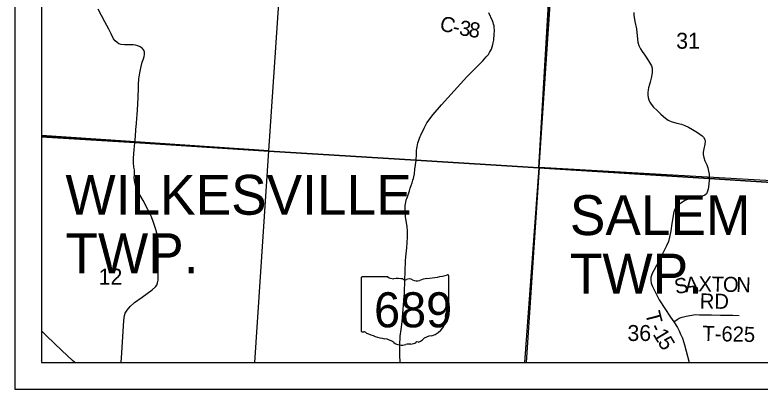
# Model space of a CAD drawing. Extents: x 0 to 34, y 0 to 22.
# Drawn here: x 2 to 4.807, y 14 to 15.408 of the extents above; entities that cross this region are included whole.
import ezdxf

# ---------------------------------------------------------------- set-up
doc = ezdxf.new("R2010")
doc.units = 0
for name, color, linetype in [('GM_X_Corporation', 7, 'Continuous'), ('GM_X_County_Road_Text', 7, 'Continuous'), ('GM_X_Section_Text', 7, 'Continuous'), ('GM_X_State_Location', 7, 'Continuous'), ('GM_X_State_Route', 7, 'Continuous'), ('GM_X_State_Shield', 7, 'Continuous'), ('GM_X_Township_Road', 7, 'Continuous'), ('GM_X_Township_Road_Text', 7, 'Continuous'), ('GM_X_Township_Text', 7, 'Continuous'), ('SH_Data', 7, 'Continuous')]:
    doc.layers.add(name, color=color, linetype=linetype)

msp = doc.modelspace()

# ---------------------------------------------------------------- linework, layer by layer
at = {"layer": 'GM_X_Corporation'}
msp.add_lwpolyline([(2.1, 20.9), (2.1, 14.9497), (2.4519, 14.9275), (2.9562, 14.8958), (3.5107, 14.8614), (3.9742, 14.8327), (4.0069, 15.4088), (4.03, 15.7625), (4.0425, 15.9604), (4.0732, 16.4197), (4.1048, 16.7908), (4.1087, 16.8515), (4.1128, 16.8828), (4.1159, 16.9184), (4.1162, 16.9397), (4.1215, 17.0136), (4.1603, 17.6679)], dxfattribs=at)
for points in [[(2.1, 15.9854), (2.1, 14.9539), (2.9567, 14.8961), (3.0263, 15.9353)], [(4.0444, 15.8589), (5.0732, 15.7926), (5.0032, 14.775), (3.9752, 14.8336)], [(2.1, 14.9539), (2.1, 14.1), (2.9042, 14.1), (2.9567, 14.8961)], [(3.9197, 14.1), (8.9, 14.1), (8.9, 14.5351), (8.0587, 14.59), (7.0121, 14.6499), (6.0453, 14.7107), (5.2037, 14.7544), (4.6148, 14.7919), (3.9742, 14.8327)], [(3.9255, 14.1), (4.958, 14.1), (5.0032, 14.775), (3.9752, 14.8336)]]:
    msp.add_lwpolyline(points, close=True, dxfattribs=at)
at = {"layer": 'GM_X_State_Route'}
for points in [[(3.4508, 14.1), (3.4502, 14.1289), (3.45, 14.162), (3.4497, 14.177), (3.4507, 14.188), (3.4518, 14.1994), (3.4549, 14.224), (3.4575, 14.2433), (3.4593, 14.2539), (3.4672, 14.3623), (3.4693, 14.4102), (3.4705, 14.4428), (3.4713, 14.4824), (3.4726, 14.4977), (3.4762, 14.5314), (3.4777, 14.5517), (3.4787, 14.5719), (3.4787, 14.5854), (3.4787, 14.594), (3.4783, 14.6008), (3.4778, 14.6059), (3.4773, 14.611), (3.4759, 14.6195), (3.4729, 14.6411), (3.4715, 14.648), (3.4708, 14.6556), (3.4703, 14.6622), (3.4697, 14.6718), (3.4697, 14.6786), (3.47, 14.6844), (3.4703, 14.6908), (3.4718, 14.6969), (3.4728, 14.7021), (3.4744, 14.7119), (3.476, 14.7178), (3.4785, 14.7239), (3.486, 14.7466), (3.4895, 14.7563), (3.4927, 14.7663), (3.4963, 14.7756), (3.4993, 14.7857), (3.5011, 14.792), (3.5024, 14.7988), (3.5047, 14.8095), (3.5071, 14.8273), (3.5109, 14.8597), (3.511, 14.8609), (3.5125, 14.8847), (3.5132, 14.8973), (3.5143, 14.9053), (3.5148, 14.9116), (3.5161, 14.9198), (3.5178, 14.9266), (3.5199, 14.9333), (3.5245, 14.9448), (3.5271, 14.9507), (3.5295, 14.9562), (3.5413, 14.9816), (3.5477, 14.994), (3.5523, 15.0019), (3.575, 15.0335), (3.6065, 15.0695), (3.7027, 15.175), (3.7273, 15.2003), (3.7621, 15.2352), (3.7751, 15.2505), (3.7837, 15.2598), (3.7881, 15.2667), (3.7918, 15.2729), (3.7953, 15.2793), (3.7982, 15.2884), (3.8, 15.2968), (3.8018, 15.303), (3.8035, 15.3128), (3.8043, 15.3207), (3.8051, 15.3295), (3.8059, 15.3383), (3.8064, 15.346), (3.8062, 15.3526), (3.8059, 15.3601), (3.8049, 15.3676), (3.8031, 15.3737), (3.801, 15.3801), (3.799, 15.3863), (3.7855, 15.4156)], [(2.2253, 14.1), (2.2166, 14.1079), (2.1773, 14.1453), (2.1198, 14.1993), (2.1095, 14.21), (2.1, 14.2193)]]:
    msp.add_lwpolyline(points, dxfattribs=at)
at = {"layer": 'GM_X_State_Shield'}
for p, q in [((3.3044, 14.4184), (3.3044, 14.2183)), ((3.4042, 14.4219), (3.3077, 14.4219)), ((3.634, 14.3221), (3.634, 14.4268)), ((3.634, 14.3222), (3.634, 14.3221))]:
    msp.add_line(p, q, dxfattribs=at)
for centre, major_axis, start_param, end_param in [((3.5166, 14.6947), (0.3495, 0), 4.814394, 5.042369), ((3.6304, 14.4272), (0.00367, 0), 6.141152, 7.989035), ((3.3082, 14.4188), (0.00382, 0), 1.712693, 3.28349), ((3.4272, 14.4451), (0.037, 0), 4.042523, 4.731795), ((3.4395, 14.3095), (0.133, 0), 1.404758, 1.657858), ((3.4696, 14.4199), (0.0107, 0), 3.836095, 5.185415), ((3.4853, 14.3967), (0.0222, 0), 0.950623, 2.079405), ((3.514, 14.4285), (0.0267, 0), 4.081561, 5.145723), ((3.5612, 14.3607), (0.0703, 0), 1.699011, 2.107814), ((3.6332, 14.3144), (0.00568, 0), 1.883978, 3.671073), ((3.6301, 14.3217), (0.00393, 0), 5.05454, 6.418171), ((3.6472, 14.2783), (0.0248, 0), 2.387724, 3.262537), ((3.597, 14.3012), (0.0341, 0), 5.934695, 6.695948), ((3.5362, 14.265), (0.0874, 0), 5.101752, 6.440018), ((3.3082, 14.2179), (0.00385, 0), 3.00124, 4.508301), ((3.3088, 14.2383), (0.0294, 0), 4.665946, 4.897461), ((3.3148, 14.2067), (0.0106, 0), 0.519207, 1.627899), ((3.4487, 14.3865), (0.2524, 0), 4.195997, 4.488961), ((3.3734, 14.1284), (0.079, 0), 0.823519, 1.323587), ((3.4914, 14.1908), (0.0267, 0), 4.691044, 5.507374), ((3.5156, 14.1714), (0.00752, 0), 1.147584, 2.315152), ((3.5124, 14.1989), (0.0282, 0), 4.937069, 5.64225), ((3.573, 14.1621), (0.0479, 0), 1.647645, 2.488434), ((3.4588, 14.2058), (0.0501, 0), 4.026481, 4.996735), ((3.4878, 14.1366), (0.0412, 0), 1.495662, 1.94098)]:
    msp.add_ellipse(centre, major_axis=major_axis, ratio=0.8, start_param=start_param, end_param=end_param, dxfattribs=at)
at = {"layer": 'GM_X_Township_Road'}
for points in [[(2.4521, 14.927), (2.4537, 14.9508), (2.456, 14.977), (2.4584, 15), (2.4594, 15.0193), (2.4603, 15.0322), (2.4626, 15.0706), (2.4657, 15.1298), (2.4658, 15.1459), (2.4672, 15.167), (2.4695, 15.1827), (2.4721, 15.1963), (2.4752, 15.2141), (2.4791, 15.2301), (2.4838, 15.2433), (2.4865, 15.2522), (2.4887, 15.2594), (2.4882, 15.2684), (2.4857, 15.2758), (2.4795, 15.2828), (2.4721, 15.288), (2.4632, 15.2922), (2.4546, 15.2948), (2.4454, 15.2962), (2.4131, 15.2959), (2.4006, 15.2971), (2.3917, 15.2999), (2.385, 15.3044), (2.3782, 15.311), (2.3716, 15.3184), (2.3623, 15.3371), (2.3532, 15.3543), (2.3387, 15.3827), (2.314, 15.4304)], [(4.3314, 15.4177), (4.3309, 15.4073), (4.3355, 15.3836), (4.3411, 15.356), (4.3438, 15.3292), (4.3468, 15.3058), (4.3499, 15.2929), (4.3564, 15.2803), (4.3628, 15.2701), (4.3724, 15.2563), (4.3868, 15.2354), (4.3947, 15.2233), (4.3978, 15.2162), (4.4, 15.208), (4.4006, 15.2005), (4.4, 15.1902), (4.3963, 15.1703), (4.3927, 15.1551), (4.3905, 15.1458), (4.3866, 15.1338), (4.3849, 15.1256), (4.384, 15.1163), (4.3842, 15.1056), (4.3854, 15.0979), (4.3874, 15.0883), (4.3911, 15.0794), (4.3961, 15.0717), (4.4056, 15.0612), (4.4189, 15.0489), (4.4337, 15.0349), (4.4434, 15.0254), (4.4511, 15.0195), (4.4609, 15.0116), (4.4718, 15.0075), (4.4935, 15.0006), (4.5108, 14.9966), (4.523, 14.9921), (4.5374, 14.9852), (4.5524, 14.9767), (4.5707, 14.9661), (4.5806, 14.9597), (4.5889, 14.9534), (4.5942, 14.9479), (4.5987, 14.9388), (4.6001, 14.9318), (4.5991, 14.9213), (4.5948, 14.9047), (4.5928, 14.8917), (4.5928, 14.8825), (4.5948, 14.8716), (4.5987, 14.8594), (4.606, 14.8442), (4.6098, 14.8322), (4.6133, 14.82), (4.6147, 14.8085), (4.6153, 14.7999), (4.615, 14.7914), (4.615, 14.7893)], [(2.4008, 14.1), (2.4034, 14.136), (2.4066, 14.1978), (2.4103, 14.2565), (2.4114, 14.2685), (2.413, 14.2775), (2.4158, 14.2858), (2.4229, 14.2969), (2.4339, 14.3103), (2.4508, 14.3263), (2.4791, 14.3464), (2.4982, 14.3599), (2.5175, 14.374), (2.53, 14.3842), (2.5344, 14.3906), (2.5377, 14.3998), (2.5391, 14.4105), (2.5393, 14.422), (2.5399, 14.4338), (2.5396, 14.4599), (2.5397, 14.5211), (2.5399, 14.5597), (2.5379, 14.572), (2.5304, 14.6005), (2.5216, 14.6273), (2.5141, 14.6482), (2.5006, 14.6757), (2.483, 14.7094), (2.4709, 14.7313), (2.456, 14.7615), (2.4537, 14.7689), (2.4516, 14.778), (2.4494, 14.7948), (2.4499, 14.8057), (2.4499, 14.8246), (2.4486, 14.835), (2.4468, 14.8533), (2.4462, 14.8694), (2.4497, 14.9022), (2.4521, 14.927)], [(4.615, 14.7893), (4.6149, 14.7872), (4.6145, 14.7711), (4.612, 14.7523), (4.6082, 14.7413), (4.6047, 14.7352), (4.5991, 14.7303), (4.5903, 14.7265), (4.5544, 14.7196), (4.5404, 14.7161), (4.5234, 14.7094), (4.5114, 14.7015), (4.5002, 14.6928), (4.4921, 14.6851), (4.4864, 14.6776), (4.4818, 14.6666), (4.4749, 14.6226), (4.4708, 14.595), (4.4661, 14.5712), (4.4619, 14.5558), (4.4548, 14.539), (4.4266, 14.4834), (4.4085, 14.4491), (4.4022, 14.4377), (4.3994, 14.4308), (4.3955, 14.4193), (4.3953, 14.4088), (4.3971, 14.3988), (4.4022, 14.3862), (4.4114, 14.3659), (4.4274, 14.3357), (4.4481, 14.303), (4.4698, 14.2705), (4.4826, 14.2525), (4.4956, 14.2313), (4.5021, 14.2186), (4.5071, 14.2072), (4.5142, 14.1914), (4.5226, 14.1664), (4.5399, 14.1)], [(4.4826, 14.2525), (4.4952, 14.2618), (4.5025, 14.2664), (4.513, 14.2707), (4.5289, 14.2744), (4.5497, 14.2784), (4.5619, 14.2802), (4.5786, 14.28), (4.6237, 14.2788), (4.6582, 14.2784), (4.7038, 14.2779), (4.7283, 14.2769)]]:
    msp.add_lwpolyline(points, dxfattribs=at)
at = {"layer": 'GM_X_Township_Text'}
for points in [[(4.1603, 17.6679), (4.1215, 17.0136), (4.1162, 16.9397), (4.1159, 16.9184), (4.1128, 16.8828), (4.1087, 16.8515), (4.1048, 16.7908), (4.0732, 16.4197), (4.0425, 15.9604), (4.03, 15.7625), (4.0069, 15.4088), (3.9742, 14.8327), (3.9197, 14.1)], [(3.9742, 14.8327), (3.5107, 14.8614), (2.9562, 14.8958), (2.4519, 14.9275), (2.1, 14.9497)], [(3.9742, 14.8327), (4.6148, 14.7919), (5.2037, 14.7544), (6.0453, 14.7107), (7.0121, 14.6499), (8.0587, 14.59), (8.9, 14.5351)]]:
    msp.add_lwpolyline(points, dxfattribs=at)
at = {"layer": 'SH_Data'}
for p, q in [((2, 21), (2, 14)), ((2.1, 20.9), (2.1, 14.1)), ((2.0955, 14.1059), (2.0955, 14.1059)), ((2.1, 14.1), (8.9, 14.1)), ((2, 14), (9, 14))]:
    msp.add_line(p, q, dxfattribs=at)

# ---------------------------------------------------------------- texts
at = {"layer": 'GM_X_County_Road_Text'}
for s, rotation, p in [('C', 343.3217, (3.5958, 15.3529)), ('3', 350.4047, (3.6708, 15.333)), ('-', 348.3809, (3.6458, 15.3382)), ('8', 351.5623, (3.7066, 15.327))]:
    msp.add_text(s, height=0.0568, rotation=rotation, dxfattribs=at).set_placement(p)
at = {"layer": 'GM_X_Section_Text'}
for s, p in [('31', (4.491, 15.281)), ('12', (2.3153, 14.393)), ('36', (4.3073, 14.181))]:
    msp.add_text(s, height=0.06, rotation=0, dxfattribs=at).set_placement(p)
at = {"layer": 'GM_X_State_Location'}
msp.add_text('689', height=0.000189, rotation=0, dxfattribs=at).set_placement((3.3986, 14.2913))
for s in ['s', 'r']:
    msp.add_text(s, height=0.000189, dxfattribs=at).set_placement((3.4655, 14.305))
at = {"layer": 'GM_X_State_Shield'}
msp.add_text('689', height=0.13184, dxfattribs=at).set_placement((3.3529, 14.2324))
at = {"layer": 'GM_X_Township_Road_Text'}
for s, height, rotation, p in [('S', 0.0568, 10.8216, (4.4899, 14.3568)), ('A', 0.0568, 4.9164, (4.526, 14.3638)), ('X', 0.0568, 358.8889, (4.5742, 14.368)), ('T', 0.0568, 358.8881, (4.6242, 14.367)), ('O', 0.0568, 358.888, (4.6667, 14.3662)), ('N', 0.0568, 358.8889, (4.7167, 14.3652)), ('RD', 0.05682, 359.0212, (4.5794, 14.3033)), ('T', 0.0568, 284.3308, (4.3738, 14.2856)), ('-', 0.0568, 295.7214, (4.3885, 14.2329)), ('T-625', 0.05682, 358.6095, (4.5892, 14.1816)), ('1', 0.0568, 300.9462, (4.4013, 14.2069)), ('5', 0.0568, 301.315, (4.4195, 14.1765))]:
    msp.add_text(s, height=height, rotation=rotation, dxfattribs=at).set_placement(p)
at = {"layer": 'GM_X_Township_Text'}
for s, p in [('WILKESVILLE', (2.1904, 14.6562)), ('SALEM', (4.0905, 14.5795)), ('TWP.', (2.1904, 14.4362)), ('TWP.', (4.0905, 14.3595))]:
    msp.add_text(s, height=0.15, rotation=0, dxfattribs=at).set_placement(p)

doc.saveas('drawing.dxf')
